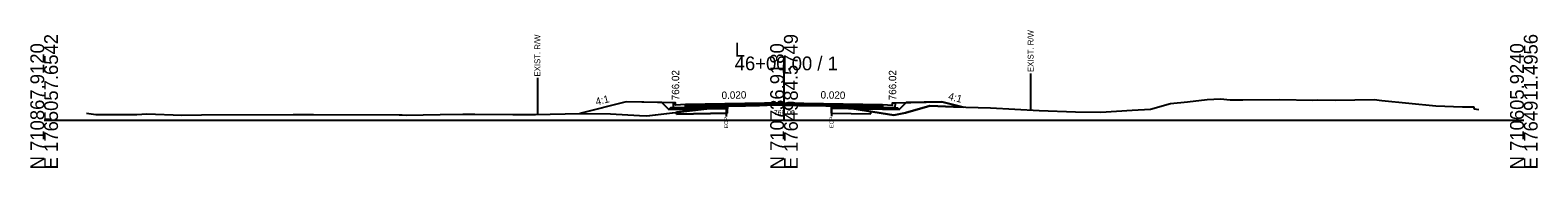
# Model space of a CAD drawing. Extents: x -26 to 5303, y -10 to 9578.
# Drawn here: x 2997.2 to 3302.8, y 5990.3 to 6018.3 of the extents above; entities that cross this region are included whole.
import ezdxf

# ---------------------------------------------------------------- set-up
doc = ezdxf.new("R2010")
doc.units = 0
for name, color, linetype in [('Default', 7, 'Continuous'), ('Exist CMT Pavement', 7, 'Continuous'), ('Exist Cross Section Cell', 7, 'Continuous'), ('Exist XS Ground Line', 7, 'Continuous'), ('Old_Level_10', 7, 'Continuous'), ('Old_Level_3', 7, 'Continuous'), ('Prop CMT Conc Surface', 7, 'Continuous'), ('Prop CMT Concrete Structures', 7, 'Continuous'), ('Prop CMT Pvmt Course 1', 7, 'Continuous'), ('Prop CMT Pvmt Course 1 CG', 7, 'Continuous'), ('Prop CMT Pvmt Course 2', 7, 'Continuous'), ('Prop CMT Pvmt Course 3', 7, 'Continuous'), ('Prop CMT Pvmt Surface', 7, 'Continuous'), ('Prop CMT Slope Grass', 7, 'Continuous'), ('Prop CMT Subgrade Earthwork', 7, 'Continuous'), ('Prop Shade Light', 7, 'Continuous'), ('Prop XS Earthwork Shape', 7, 'Continuous'), ('Prop XS Hydro Elevations', 7, 'Continuous'), ('Prop XS SE Text', 7, 'Continuous'), ('Prop XS Side Slope Text', 7, 'Continuous'), ('Prop XS Wedging', 7, 'Continuous'), ('Scratch_Level_5', 7, 'Continuous')]:
    doc.layers.add(name, color=color, linetype=linetype)

msp = doc.modelspace()

# ---------------------------------------------------------------- linework, layer by layer
at = {"layer": 'Exist CMT Pavement'}
msp.add_lwpolyline([(3138.54, 6002.82), (3138.77, 6002.86), (3139.29, 6002.88), (3140.07, 6002.89), (3141.43, 6002.91), (3142.18, 6002.93), (3143.75, 6002.98), (3145.04, 6003), (3146.56, 6003.05), (3147.61, 6003.09), (3149.12, 6003.09), (3149.49, 6003.08), (3150, 6003.06), (3150.76, 6003.03), (3151.1, 6003.03), (3151.69, 6003.01), (3152.93, 6002.99), (3153.63, 6002.99), (3154.77, 6002.98), (3156.82, 6002.94), (3158.45, 6002.92), (3158.8, 6002.91), (3159.64, 6002.86)], dxfattribs=at)
at = {"layer": 'Exist Cross Section Cell'}
for p, q in [((3150, 6000), (3150, 6012.91)), ((3000, 6000), (3150, 6000)), ((3150, 6000), (3300, 6000))]:
    msp.add_line(p, q, dxfattribs=at)
at = {"layer": 'Exist XS Ground Line'}
msp.add_lwpolyline([(3008.59, 6001.41), (3010.46, 6001.15), (3018.79, 6001.13), (3020.84, 6001.27), (3027.91, 6001.03), (3031.93, 6001.05), (3050.49, 6001.14), (3050.95, 6001.17), (3054.61, 6001.12), (3071.96, 6001.05), (3072.59, 6001.07), (3073.39, 6001.03), (3080.27, 6001.14), (3084.91, 6001.24), (3087.31, 6001.23), (3095.02, 6001.12), (3099.61, 6001.14), (3108.61, 6001.37), (3114.79, 6001.27), (3120.72, 6000.93), (3122.21, 6000.88), (3136.62, 6002.59), (3138.26, 6002.77), (3138.77, 6002.86), (3139.29, 6002.88), (3140.07, 6002.89), (3141.43, 6002.91), (3142.18, 6002.93), (3143.12, 6002.95), (3145.04, 6003), (3146.56, 6003.05), (3147.61, 6003.09), (3149.12, 6003.09), (3149.49, 6003.08), (3150, 6003.06), (3150.76, 6003.03), (3151.69, 6003.01), (3152.93, 6002.99), (3153.63, 6002.99), (3156.07, 6002.95), (3156.82, 6002.94), (3158.45, 6002.92), (3158.8, 6002.91), (3159.64, 6002.86), (3162.49, 6002.54), (3172.29, 6001.03), (3174.64, 6001.51), (3179.6, 6002.9), (3184.37, 6002.68), (3191.84, 6002.46), (3201.75, 6001.97), (3209.07, 6001.65), (3214.24, 6001.61), (3220.59, 6002), (3224.32, 6002.2), (3228.33, 6003.39), (3231.78, 6003.71), (3235.79, 6004.19), (3238.47, 6004.3), (3240.45, 6004.1), (3243.06, 6004.14), (3250.5, 6004.19), (3257.24, 6004.07), (3258.1, 6004.1), (3261.84, 6004.04), (3269.64, 6004.2), (3271.19, 6004), (3282.15, 6002.9), (3287.58, 6002.69), (3289.78, 6002.7), (3289.9, 6002.26), (3290.86, 6002.17)], dxfattribs=at)
at = {"layer": 'Old_Level_10'}
for p, q in [((3100, 6008.55), (3100, 6001.15)), ((3200, 6009.46), (3200, 6002.06)), ((3138.26, 6002.77), (3138.26, 6000.72)), ((3159.64, 6002.86), (3159.64, 6000.81))]:
    msp.add_line(p, q, dxfattribs=at)
at = {"layer": 'Prop CMT Conc Surface'}
for points in [[(3128, 6003.02), (3128, 6003.52), (3127.5, 6003.52)], [(3130, 6003.14), (3128, 6003.02)], [(3170, 6003.14), (3172, 6003.02)], [(3172, 6003.02), (3172.01, 6003.52), (3172.51, 6003.52)]]:
    msp.add_lwpolyline(points, dxfattribs=at)
at = {"layer": 'Prop CMT Concrete Structures'}
for points in [[(3130, 6003.14), (3128, 6003.02), (3128, 6003.52), (3127.5, 6003.52)], [(3127.5, 6003.52), (3127.5, 6002.5), (3130, 6002.55)], [(3130, 6002.55), (3130, 6003.14)], [(3170, 6003.14), (3172, 6003.02), (3172.01, 6003.52), (3172.51, 6003.52)], [(3172.51, 6003.52), (3172.5, 6002.5), (3170, 6002.55)], [(3170, 6002.55), (3170, 6003.14)]]:
    msp.add_lwpolyline(points, dxfattribs=at)
at = {"layer": 'Prop CMT Pvmt Course 1'}
for points in [[(3150, 6003.54), (3130, 6003.14)], [(3130, 6003.14), (3130, 6002.89)], [(3130, 6002.89), (3138.54, 6003.06)], [(3138.54, 6003.06), (3150, 6003.29)], [(3138.54, 6003.06), (3138.54, 6003.06)], [(3150, 6003.29), (3150, 6003.54)], [(3150, 6003.54), (3170, 6003.14)], [(3150, 6003.29), (3150, 6003.29), (3150, 6003.29)], [(3159.64, 6003.09), (3150, 6003.29)], [(3170, 6002.89), (3159.64, 6003.09)], [(3159.64, 6003.09), (3159.64, 6003.09)], [(3170, 6003.14), (3170, 6002.89)]]:
    msp.add_lwpolyline(points, dxfattribs=at)
at = {"layer": 'Prop CMT Pvmt Course 1 CG'}
for points in [[(3130, 6002.55), (3127, 6002.49), (3126.66, 6002.15)], [(3130, 6002.55), (3127, 6002.49), (3126.66, 6002.15)], [(3126.66, 6002.15), (3130, 6002.22)], [(3126.66, 6002.15), (3130, 6002.22)], [(3130, 6002.22), (3130, 6002.55)], [(3130, 6002.22), (3130, 6002.55)], [(3170, 6002.55), (3173, 6002.49), (3173.34, 6002.15)], [(3170, 6002.22), (3170, 6002.55)], [(3173.34, 6002.15), (3170, 6002.22)]]:
    msp.add_lwpolyline(points, dxfattribs=at)
at = {"layer": 'Prop CMT Pvmt Course 2'}
for points in [[(3138.54, 6003.06), (3130, 6002.89)], [(3130, 6002.89), (3130, 6002.55)], [(3130, 6002.55), (3138.54, 6002.73)], [(3138.54, 6002.73), (3138.54, 6003.06)], [(3159.64, 6002.76), (3159.64, 6003.09)], [(3159.64, 6003.09), (3170, 6002.89)], [(3170, 6002.55), (3159.64, 6002.76)], [(3170, 6002.89), (3170, 6002.55)]]:
    msp.add_lwpolyline(points, dxfattribs=at)
at = {"layer": 'Prop CMT Pvmt Course 3'}
for points in [[(3138.54, 6002.73), (3130, 6002.55)], [(3130, 6002.55), (3130, 6002.22)], [(3130, 6002.22), (3138.54, 6002.39)], [(3138.54, 6002.39), (3138.54, 6002.73)], [(3159.64, 6002.76), (3170, 6002.55)], [(3159.64, 6002.43), (3159.64, 6002.76)], [(3170, 6002.22), (3159.64, 6002.43)], [(3170, 6002.55), (3170, 6002.22)]]:
    msp.add_lwpolyline(points, dxfattribs=at)
at = {"layer": 'Prop CMT Pvmt Surface'}
for points in [[(3150, 6003.54), (3130, 6003.14)], [(3150, 6003.54), (3170, 6003.14)]]:
    msp.add_lwpolyline(points, dxfattribs=at)
at = {"layer": 'Prop CMT Slope Grass'}
for points in [[(3127.5, 6003.52), (3118, 6003.71), (3108.63, 6001.37)], [(3172.51, 6003.52), (3182.01, 6003.71), (3186.34, 6002.63)]]:
    msp.add_lwpolyline(points, dxfattribs=at)
at = {"layer": 'Prop CMT Subgrade Earthwork'}
for p, q in [((3138.54, 6002.39), (3138.54, 6002.82)), ((3159.64, 6002.43), (3159.64, 6002.86))]:
    msp.add_line(p, q, dxfattribs=at)
for points in [[(3130, 6002.22), (3126.66, 6002.15), (3125.25, 6003.56)], [(3138.54, 6002.39), (3130, 6002.22)], [(3159.64, 6002.43), (3170, 6002.22)], [(3170, 6002.22), (3173.34, 6002.15), (3174.75, 6003.56)]]:
    msp.add_lwpolyline(points, dxfattribs=at)
at = {"layer": 'Prop Shade Light'}
for p, q in [((3134.21, 6002.31), (3128.2, 6001.59)), ((3128.2, 6001.18), (3128.2, 6001.59)), ((3128.2, 6001.59), (3128.2, 6001.18)), ((3128.2, 6001.18), (3138.54, 6001.39)), ((3137.47, 6002.37), (3136.03, 6002.34)), ((3138.54, 6002.39), (3137.47, 6002.37)), ((3138.54, 6001.39), (3138.54, 6002.39)), ((3138.54, 6001.39), (3138.54, 6002.39)), ((3159.64, 6001.43), (3159.64, 6002.43)), ((3159.64, 6002.43), (3159.64, 6001.43)), ((3160.49, 6002.41), (3159.64, 6002.43)), ((3159.64, 6001.43), (3167.59, 6001.27)), ((3167.59, 6001.76), (3163.76, 6002.35)), ((3167.59, 6001.27), (3167.59, 6001.76)), ((3167.59, 6001.27), (3167.59, 6001.76))]:
    msp.add_line(p, q, dxfattribs=at)
for points in [[(3138.54, 6001.39), (3128.2, 6001.18)], [(3136.03, 6002.34), (3134.58, 6002.31), (3134.21, 6002.31)], [(3159.64, 6001.43), (3167.59, 6001.27)], [(3163.76, 6002.35), (3163.26, 6002.36), (3161.88, 6002.38), (3160.49, 6002.41)]]:
    msp.add_lwpolyline(points, dxfattribs=at)
at = {"layer": 'Prop XS Earthwork Shape'}
for points in [[(3108.63, 6001.37), (3114.79, 6001.27), (3120.72, 6000.93), (3122.21, 6000.88), (3134.21, 6002.31), (3130, 6002.22), (3126.66, 6002.15), (3125.25, 6003.56), (3118, 6003.71)], [(3120.72, 6000.93), (3122.21, 6000.88), (3134.21, 6002.31), (3130, 6002.22), (3126.66, 6002.15), (3125.25, 6003.56), (3118, 6003.71), (3108.63, 6001.37), (3114.79, 6001.27)], [(3184.37, 6002.68), (3186.34, 6002.63), (3182.01, 6003.71), (3174.75, 6003.56), (3173.34, 6002.15), (3170, 6002.22), (3163.76, 6002.35), (3172.29, 6001.03), (3174.64, 6001.51), (3179.6, 6002.9)], [(3182.01, 6003.71), (3186.34, 6002.63), (3184.37, 6002.68), (3179.6, 6002.9), (3174.64, 6001.51), (3172.29, 6001.03), (3163.76, 6002.35), (3170, 6002.22), (3173.34, 6002.15), (3174.75, 6003.56)], [(3138.54, 6002.39), (3138.54, 6002.82), (3138.26, 6002.77), (3136.62, 6002.59), (3134.21, 6002.31)], [(3134.21, 6002.31), (3136.62, 6002.59), (3138.26, 6002.77), (3138.54, 6002.82), (3138.54, 6002.39)], [(3162.49, 6002.54), (3163.76, 6002.35), (3159.64, 6002.43), (3159.64, 6002.86)]]:
    msp.add_lwpolyline(points, close=True, dxfattribs=at)
at = {"layer": 'Prop XS Wedging'}
for points in [[(3138.26, 6002.77), (3138.26, 6003.05), (3138.77, 6003.06), (3139.28, 6003.07), (3140.07, 6003.09), (3141.43, 6003.12), (3142.18, 6003.13), (3143.75, 6003.16), (3145.04, 6003.19), (3146.56, 6003.22), (3147.61, 6003.24), (3149.12, 6003.27), (3149.49, 6003.28), (3150, 6003.29), (3150.76, 6003.27), (3151.1, 6003.27), (3151.69, 6003.25), (3152.93, 6003.23), (3153.63, 6003.22), (3154.77, 6003.19), (3156.83, 6003.15), (3158.45, 6003.12), (3158.8, 6003.11), (3159.64, 6003.1), (3159.64, 6002.86), (3158.8, 6002.91), (3158.45, 6002.92), (3156.83, 6002.94), (3154.77, 6002.98), (3153.63, 6002.99), (3152.93, 6002.99), (3151.69, 6003.01), (3151.1, 6003.03), (3150.76, 6003.03), (3150, 6003.06), (3149.49, 6003.08), (3149.12, 6003.09), (3147.61, 6003.09), (3146.56, 6003.05), (3145.04, 6003), (3143.75, 6002.98), (3142.18, 6002.93), (3141.43, 6002.91), (3140.07, 6002.89), (3139.28, 6002.88), (3138.77, 6002.86)], [(3138.26, 6002.77), (3138.26, 6003.05), (3138.72, 6003.06), (3138.89, 6002.89)], [(3149.41, 6003.08), (3149.61, 6003.28), (3150, 6003.29), (3150.76, 6003.27), (3151.1, 6003.27), (3151.69, 6003.25), (3152.93, 6003.23), (3153.63, 6003.22), (3154.77, 6003.19), (3156.83, 6003.15), (3157.03, 6003.15), (3157.24, 6002.94), (3156.83, 6002.94), (3154.77, 6002.98), (3153.63, 6002.99), (3152.93, 6002.99), (3151.69, 6003.01), (3151.1, 6003.03), (3150.76, 6003.03), (3150, 6003.06), (3149.49, 6003.08)], [(3158.83, 6002.91), (3159.02, 6003.11), (3159.64, 6003.1), (3159.64, 6002.86)]]:
    msp.add_lwpolyline(points, close=True, dxfattribs=at)
at = {"layer": 'Scratch_Level_5'}
for p, q in [((3134.58, 6002.31), (3134.63, 6002.36)), ((3136.03, 6002.34), (3136.23, 6002.55)), ((3137.47, 6002.37), (3137.82, 6002.72)), ((3160.49, 6002.41), (3160.81, 6002.73)), ((3161.88, 6002.38), (3162.08, 6002.59)), ((3163.26, 6002.36), (3163.32, 6002.41))]:
    msp.add_line(p, q, dxfattribs=at)

# ---------------------------------------------------------------- texts
at = {"layer": 'Default'}
msp.add_text('-', height=0.0001, dxfattribs=at).set_placement((3000, 6000))
at = {"layer": 'Exist Cross Section Cell'}
for s, p in [('E 1765057.6542', (3002.8, 5990)), ('E 1764984.5749', (3152.8, 5990)), ('E 1764911.4956', (3302.8, 5990)), ('N 710867.9120', (3000, 5990)), ('N 710736.9180', (3150, 5990)), ('N 710605.9240', (3300, 5990))]:
    msp.add_text(s, height=2.8, rotation=90, dxfattribs=at).set_placement(p)
for s, p in [('46+00.00 / 1', (3140, 6010.11)), ('L', (3140, 6012.91))]:
    msp.add_text(s, height=2.8, dxfattribs=at).set_placement(p)
at = {"layer": 'Old_Level_10'}
for s, height, p in [('EXIST. R/W', 1.181, (3100.59, 6008.85)), ('EXIST. R/W', 1.181, (3200.59, 6009.76)), ('EOP', 0.787, (3160.03, 5998.41)), ('EOP', 0.787, (3138.66, 5998.32))]:
    msp.add_text(s, height=height, rotation=90, dxfattribs=at).set_placement(p)
at = {"layer": 'Old_Level_3'}
msp.add_text('766.06', height=1, dxfattribs=at).set_placement((3147.95, 6001.06))
at = {"layer": 'Prop XS Hydro Elevations'}
for p in [(3128.75, 6004.02), (3172.75, 6004.02)]:
    msp.add_text('766.02', height=1.5, rotation=90, dxfattribs=at).set_placement(p)
at = {"layer": 'Prop XS SE Text'}
for rotation, p in [(1.1458, (3137.36, 6004.29)), (358.8542, (3157.4, 6004.39))]:
    msp.add_text('0.020', height=1.5, rotation=rotation, dxfattribs=at).set_placement(p)
at = {"layer": 'Prop XS Side Slope Text'}
for rotation, p in [(14.0362, (3111.98, 6002.98)), (345.9638, (3183.2, 6004.18))]:
    msp.add_text('4:1', height=1.5, rotation=rotation, dxfattribs=at).set_placement(p)

doc.saveas('drawing.dxf')
